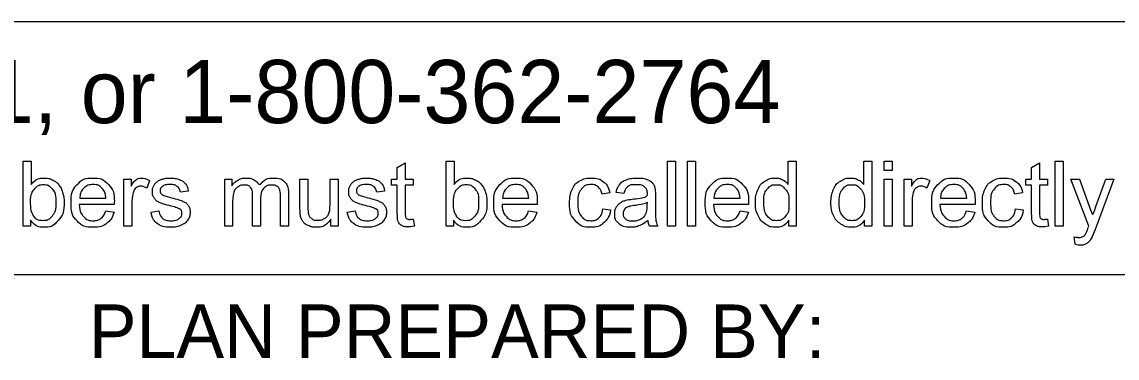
# Model space of a CAD drawing. Extents: x 0 to 96.2, y -27.5 to 31.3.
# Drawn here: x 45.936 to 48.797, y 1.82 to 2.697 of the extents above; entities that cross this region are included whole.
import ezdxf

# ---------------------------------------------------------------- set-up
doc = ezdxf.new("R2010")
doc.units = 0
doc.layers.add('TB1', color=7, linetype='Continuous')

msp = doc.modelspace()

# ---------------------------------------------------------------- linework, layer by layer
at = {"layer": 'TB1'}
for p, q in [((49.4609, 2.6972), (44.2359, 2.6972)), ((49.4609, 2.0372), (44.2359, 2.0372))]:
    msp.add_line(p, q, dxfattribs=at)
for points in [[(45.9585, 2.1641), (45.9393, 2.1641), (45.9393, 2.3335), (45.9601, 2.3335), (45.9601, 2.2731)], [(46.9163, 2.2001), (46.9163, 2.2708), (46.901, 2.2708), (46.901, 2.2869), (46.9163, 2.2869), (46.9163, 2.3173), (46.9371, 2.3298), (46.9371, 2.2869), (46.9579, 2.2869), (46.9579, 2.2708), (46.9371, 2.2708), (46.9371, 2.1988)], [(47.0631, 2.1641), (47.0439, 2.1641), (47.0439, 2.3335), (47.0647, 2.3335), (47.0647, 2.2731)], [(47.6223, 2.1641), (47.6223, 2.3335), (47.6431, 2.3335), (47.6431, 2.1641), (47.6223, 2.1641)], [(47.6749, 2.1641), (47.6749, 2.3335), (47.6957, 2.3335), (47.6957, 2.1641), (47.6749, 2.1641)], [(47.9376, 2.2728), (47.9376, 2.3335), (47.9584, 2.3335), (47.9584, 2.1641), (47.9392, 2.1641)], [(48.1349, 2.2728), (48.1349, 2.3335), (48.1557, 2.3335), (48.1557, 2.1641), (48.1365, 2.1641)], [(48.1885, 2.3096), (48.1885, 2.3335), (48.2093, 2.3335), (48.2093, 2.3096), (48.1885, 2.3096)], [(48.5734, 2.2001), (48.5734, 2.2708), (48.558, 2.2708), (48.558, 2.2869), (48.5734, 2.2869), (48.5734, 2.3173), (48.5942, 2.3298), (48.5942, 2.2869), (48.615, 2.2869), (48.615, 2.2708), (48.5942, 2.2708), (48.5942, 2.1988)], [(48.6349, 2.1641), (48.6349, 2.3335), (48.6556, 2.3335), (48.6556, 2.1641), (48.6349, 2.1641)], [(46.2023, 2.1641), (46.2023, 2.2869), (46.221, 2.2869), (46.221, 2.2683)], [(46.2689, 2.283), (46.2617, 2.2637)], [(46.4654, 2.1641), (46.4654, 2.2869), (46.484, 2.2869), (46.484, 2.2696)], [(46.6621, 2.2109), (46.6621, 2.2869), (46.6829, 2.2869), (46.6829, 2.2189)], [(46.7407, 2.2212), (46.7407, 2.2869), (46.7615, 2.2869), (46.7615, 2.1641), (46.7429, 2.1641)], [(48.1885, 2.1641), (48.1885, 2.2869), (48.2093, 2.2869), (48.2093, 2.1641), (48.1885, 2.1641)], [(48.2407, 2.1641), (48.2407, 2.2869), (48.2594, 2.2869), (48.2594, 2.2683)], [(48.3073, 2.283), (48.3, 2.2637)], [(48.7227, 2.164), (48.676, 2.2869), (48.6985, 2.2869), (48.724, 2.216)], [(48.7415, 2.2153), (48.7677, 2.2869), (48.7885, 2.2869), (48.7419, 2.162)], [(46.0866, 2.2372), (46.1552, 2.2372)], [(46.3704, 2.2551), (46.35, 2.2524)], [(46.5592, 2.2354), (46.5592, 2.1641), (46.5384, 2.1641), (46.5384, 2.2438)], [(46.6319, 2.2484), (46.6319, 2.1641), (46.6111, 2.1641), (46.6111, 2.2414)], [(46.8833, 2.2551), (46.8629, 2.2524)], [(47.1912, 2.2372), (47.2598, 2.2372)], [(47.4715, 2.2508), (47.4512, 2.2477)], [(47.5082, 2.2491), (47.4878, 2.2518)], [(47.5906, 2.2433), (47.5906, 2.2156)], [(47.7436, 2.2372), (47.8121, 2.2372)], [(48.3353, 2.2372), (48.4039, 2.2372)], [(48.5499, 2.2508), (48.5296, 2.2477)], [(46.177, 2.2202), (46.0855, 2.2202)], [(46.155, 2.2038), (46.1764, 2.201)], [(46.2231, 2.2284), (46.2231, 2.1641), (46.2023, 2.1641)], [(46.2729, 2.2008), (46.2935, 2.204)], [(46.4862, 2.2278), (46.4862, 2.1641), (46.4654, 2.1641)], [(46.7858, 2.2008), (46.8063, 2.204)], [(47.2816, 2.2202), (47.19, 2.2202)], [(47.2595, 2.2038), (47.281, 2.201)], [(47.4531, 2.209), (47.4735, 2.2063)], [(47.5695, 2.2181), (47.5696, 2.2257)], [(47.834, 2.2202), (47.7424, 2.2202)], [(47.8119, 2.2038), (47.8334, 2.201)], [(48.2615, 2.2284), (48.2615, 2.1641), (48.2407, 2.1641)], [(48.4257, 2.2202), (48.3341, 2.2202)], [(48.4036, 2.2038), (48.4251, 2.201)], [(48.5314, 2.209), (48.5518, 2.2063)], [(45.9585, 2.1795), (45.9585, 2.1641)], [(46.7429, 2.1641), (46.7429, 2.1822)], [(46.9579, 2.1827), (46.9609, 2.1643)], [(47.0631, 2.1795), (47.0631, 2.1641)], [(47.9392, 2.1641), (47.9392, 2.1796)], [(48.1365, 2.1641), (48.1365, 2.1796)], [(48.615, 2.1827), (48.6179, 2.1643)], [(47.5972, 2.1641), (47.5755, 2.1641)], [(48.687, 2.117), (48.6847, 2.1365)]]:
    msp.add_lwpolyline(points, dxfattribs=at)
for points, degree in [([(45.9601, 2.2731), (45.9733, 2.2896), (45.9937, 2.2896), (46.005, 2.2896), (46.0151, 2.2851), (46.0252, 2.2805), (46.0318, 2.2722), (46.0383, 2.264), (46.042, 2.2523), (46.0457, 2.2406), (46.0457, 2.2274), (46.0457, 2.1958), (46.0301, 2.1786), (46.0145, 2.1614), (45.9926, 2.1614), (45.9709, 2.1614), (45.9585, 2.1795)], 3), ([(46.1764, 2.201), (46.1714, 2.1822), (46.1576, 2.1718), (46.1439, 2.1614), (46.1225, 2.1614), (46.0956, 2.1614), (46.0798, 2.178), (46.064, 2.1946), (46.064, 2.2245), (46.064, 2.2554), (46.08, 2.2725), (46.0959, 2.2896), (46.1213, 2.2896), (46.1459, 2.2896), (46.1615, 2.2729), (46.1771, 2.2561), (46.1771, 2.2257), (46.1771, 2.2238), (46.177, 2.2202)], 3), ([(46.221, 2.2683), (46.2282, 2.2813), (46.2342, 2.2855), (46.2403, 2.2896), (46.2476, 2.2896), (46.2581, 2.2896), (46.2689, 2.283)], 3), ([(46.2935, 2.204), (46.2952, 2.1916), (46.3031, 2.185), (46.3111, 2.1784), (46.3253, 2.1784), (46.3397, 2.1784), (46.3467, 2.1843), (46.3536, 2.1901), (46.3536, 2.198), (46.3536, 2.2051), (46.3475, 2.2091), (46.3432, 2.2119), (46.3262, 2.2162), (46.3033, 2.222), (46.2944, 2.2262), (46.2856, 2.2304), (46.281, 2.2378), (46.2764, 2.2453), (46.2764, 2.2543), (46.2764, 2.2625), (46.2802, 2.2695), (46.2839, 2.2765), (46.2904, 2.2811), (46.2953, 2.2847), (46.3037, 2.2871), (46.3121, 2.2896), (46.3217, 2.2896), (46.3362, 2.2896), (46.3471, 2.2855), (46.358, 2.2813), (46.3632, 2.2742), (46.3685, 2.2671), (46.3704, 2.2551)], 3), ([(46.484, 2.2696), (46.4898, 2.2786), (46.4994, 2.2841), (46.509, 2.2896), (46.5212, 2.2896), (46.5349, 2.2896), (46.5436, 2.2839), (46.5523, 2.2783), (46.5559, 2.2681), (46.5705, 2.2896), (46.5939, 2.2896), (46.6122, 2.2896), (46.622, 2.2795), (46.6319, 2.2694), (46.6319, 2.2484)], 3), ([(46.8063, 2.204), (46.8081, 2.1916), (46.816, 2.185), (46.8239, 2.1784), (46.8382, 2.1784), (46.8526, 2.1784), (46.8595, 2.1843), (46.8665, 2.1901), (46.8665, 2.198), (46.8665, 2.2051), (46.8603, 2.2091), (46.856, 2.2119), (46.839, 2.2162), (46.8161, 2.222), (46.8073, 2.2262), (46.7984, 2.2304), (46.7938, 2.2378), (46.7893, 2.2453), (46.7893, 2.2543), (46.7893, 2.2625), (46.793, 2.2695), (46.7968, 2.2765), (46.8033, 2.2811), (46.8081, 2.2847), (46.8165, 2.2871), (46.8249, 2.2896), (46.8345, 2.2896), (46.849, 2.2896), (46.8599, 2.2855), (46.8709, 2.2813), (46.8761, 2.2742), (46.8813, 2.2671), (46.8833, 2.2551)], 3), ([(47.0647, 2.2731), (47.0778, 2.2896), (47.0983, 2.2896), (47.1096, 2.2896), (47.1197, 2.2851), (47.1298, 2.2805), (47.1364, 2.2722), (47.1429, 2.264), (47.1466, 2.2523), (47.1503, 2.2406), (47.1503, 2.2274), (47.1503, 2.1958), (47.1347, 2.1786), (47.1191, 2.1614), (47.0972, 2.1614), (47.0755, 2.1614), (47.0631, 2.1795)], 3), ([(47.281, 2.201), (47.2759, 2.1822), (47.2622, 2.1718), (47.2484, 2.1614), (47.2271, 2.1614), (47.2002, 2.1614), (47.1844, 2.178), (47.1686, 2.1946), (47.1686, 2.2245), (47.1686, 2.2554), (47.1846, 2.2725), (47.2005, 2.2896), (47.2259, 2.2896), (47.2505, 2.2896), (47.2661, 2.2729), (47.2817, 2.2561), (47.2817, 2.2257), (47.2817, 2.2238), (47.2816, 2.2202)], 3), ([(47.4735, 2.2063), (47.4701, 2.1853), (47.4563, 2.1733), (47.4425, 2.1614), (47.4224, 2.1614), (47.3972, 2.1614), (47.3819, 2.1779), (47.3665, 2.1943), (47.3665, 2.225), (47.3665, 2.2449), (47.3731, 2.2598), (47.3797, 2.2747), (47.3932, 2.2822), (47.4067, 2.2896), (47.4225, 2.2896), (47.4425, 2.2896), (47.4552, 2.2795), (47.4679, 2.2694), (47.4715, 2.2508)], 3), ([(47.4878, 2.2518), (47.4906, 2.2649), (47.4969, 2.2729), (47.5033, 2.2809), (47.5153, 2.2853), (47.5273, 2.2896), (47.5431, 2.2896), (47.5588, 2.2896), (47.5686, 2.2859), (47.5784, 2.2822), (47.5831, 2.2766), (47.5877, 2.271), (47.5895, 2.2624), (47.5906, 2.2571), (47.5906, 2.2433)], 3), ([(47.8334, 2.201), (47.8283, 2.1822), (47.8146, 2.1718), (47.8008, 2.1614), (47.7794, 2.1614), (47.7525, 2.1614), (47.7367, 2.178), (47.721, 2.1946), (47.721, 2.2245), (47.721, 2.2554), (47.7369, 2.2725), (47.7529, 2.2896), (47.7783, 2.2896), (47.8029, 2.2896), (47.8185, 2.2729), (47.8341, 2.2561), (47.8341, 2.2257), (47.8341, 2.2238), (47.834, 2.2202)], 3), ([(47.9392, 2.1796), (47.9275, 2.1614), (47.9048, 2.1614), (47.8902, 2.1614), (47.8779, 2.1695), (47.8655, 2.1776), (47.8588, 2.1921), (47.852, 2.2066), (47.852, 2.2254), (47.852, 2.2438), (47.8581, 2.2587), (47.8643, 2.2737), (47.8765, 2.2816), (47.8887, 2.2896), (47.9038, 2.2896), (47.9149, 2.2896), (47.9236, 2.2849), (47.9322, 2.2803), (47.9376, 2.2728)], 3), ([(48.1365, 2.1796), (48.1248, 2.1614), (48.1021, 2.1614), (48.0875, 2.1614), (48.0751, 2.1695), (48.0628, 2.1776), (48.0561, 2.1921), (48.0493, 2.2066), (48.0493, 2.2254), (48.0493, 2.2438), (48.0554, 2.2587), (48.0615, 2.2737), (48.0738, 2.2816), (48.086, 2.2896), (48.1011, 2.2896), (48.1122, 2.2896), (48.1208, 2.2849), (48.1295, 2.2803), (48.1349, 2.2728)], 3), ([(48.2594, 2.2683), (48.2665, 2.2813), (48.2726, 2.2855), (48.2787, 2.2896), (48.2859, 2.2896), (48.2964, 2.2896), (48.3073, 2.283)], 3), ([(48.4251, 2.201), (48.42, 2.1822), (48.4063, 2.1718), (48.3925, 2.1614), (48.3712, 2.1614), (48.3443, 2.1614), (48.3285, 2.178), (48.3127, 2.1946), (48.3127, 2.2245), (48.3127, 2.2554), (48.3287, 2.2725), (48.3446, 2.2896), (48.37, 2.2896), (48.3946, 2.2896), (48.4102, 2.2729), (48.4258, 2.2561), (48.4258, 2.2257), (48.4258, 2.2238), (48.4257, 2.2202)], 3), ([(48.5518, 2.2063), (48.5485, 2.1853), (48.5347, 2.1733), (48.5209, 2.1614), (48.5007, 2.1614), (48.4756, 2.1614), (48.4602, 2.1779), (48.4449, 2.1943), (48.4449, 2.225), (48.4449, 2.2449), (48.4515, 2.2598), (48.4581, 2.2747), (48.4716, 2.2822), (48.485, 2.2896), (48.5009, 2.2896), (48.5209, 2.2896), (48.5336, 2.2795), (48.5463, 2.2694), (48.5499, 2.2508)], 3), ([(45.9583, 2.2264), (45.9583, 2.2043), (45.9643, 2.1945), (45.9741, 2.1784), (45.9908, 2.1784), (46.0044, 2.1784), (46.0143, 2.1903), (46.0243, 2.2022), (46.0243, 2.2256), (46.0243, 2.2497), (46.0147, 2.2611), (46.0052, 2.2726), (45.9917, 2.2726), (45.9781, 2.2726), (45.9682, 2.2607), (45.9583, 2.2489), (45.9583, 2.2264)], 3), ([(46.1552, 2.2372), (46.1538, 2.2527), (46.1473, 2.2605), (46.1374, 2.2726), (46.1215, 2.2726), (46.1072, 2.2726), (46.0974, 2.2629), (46.0877, 2.2533), (46.0866, 2.2372)], 3), ([(46.2617, 2.2637), (46.2541, 2.2682), (46.2465, 2.2682), (46.2397, 2.2682), (46.2343, 2.2641), (46.2289, 2.26), (46.2266, 2.2527), (46.2231, 2.2416), (46.2231, 2.2284)], 3), ([(46.35, 2.2524), (46.3486, 2.2619), (46.342, 2.2672), (46.3353, 2.2726), (46.3232, 2.2726), (46.3088, 2.2726), (46.3027, 2.2678), (46.2966, 2.2631), (46.2966, 2.2567), (46.2966, 2.2527), (46.2991, 2.2494), (46.3017, 2.2461), (46.3071, 2.2439), (46.3102, 2.2427), (46.3255, 2.2385), (46.3476, 2.2326), (46.3563, 2.2289), (46.3651, 2.2251), (46.3701, 2.218), (46.3751, 2.2108), (46.3751, 2.2002), (46.3751, 2.1898), (46.369, 2.1806), (46.3629, 2.1715), (46.3514, 2.1664), (46.34, 2.1614), (46.3255, 2.1614), (46.3015, 2.1614), (46.289, 2.1713), (46.2764, 2.1813), (46.2729, 2.2008)], 3), ([(46.5384, 2.2438), (46.5384, 2.2577), (46.5333, 2.2646), (46.5282, 2.2715), (46.5166, 2.2715), (46.5078, 2.2715), (46.5004, 2.2669), (46.4929, 2.2623), (46.4896, 2.2534), (46.4862, 2.2445), (46.4862, 2.2278)], 3), ([(46.6111, 2.2414), (46.6111, 2.2539), (46.609, 2.2594), (46.607, 2.2648), (46.6017, 2.2682), (46.5964, 2.2715), (46.5892, 2.2715), (46.5763, 2.2715), (46.5677, 2.2629), (46.5592, 2.2543), (46.5592, 2.2354)], 3), ([(46.8629, 2.2524), (46.8615, 2.2619), (46.8548, 2.2672), (46.8482, 2.2726), (46.836, 2.2726), (46.8217, 2.2726), (46.8155, 2.2678), (46.8094, 2.2631), (46.8094, 2.2567), (46.8094, 2.2527), (46.812, 2.2494), (46.8145, 2.2461), (46.8199, 2.2439), (46.8231, 2.2427), (46.8383, 2.2385), (46.8604, 2.2326), (46.8692, 2.2289), (46.8779, 2.2251), (46.8829, 2.218), (46.8879, 2.2108), (46.8879, 2.2002), (46.8879, 2.1898), (46.8818, 2.1806), (46.8758, 2.1715), (46.8643, 2.1664), (46.8528, 2.1614), (46.8384, 2.1614), (46.8144, 2.1614), (46.8018, 2.1713), (46.7893, 2.1813), (46.7858, 2.2008)], 3), ([(47.0629, 2.2264), (47.0629, 2.2043), (47.0689, 2.1945), (47.0787, 2.1784), (47.0954, 2.1784), (47.109, 2.1784), (47.1189, 2.1903), (47.1288, 2.2022), (47.1288, 2.2256), (47.1288, 2.2497), (47.1193, 2.2611), (47.1098, 2.2726), (47.0963, 2.2726), (47.0827, 2.2726), (47.0728, 2.2607), (47.0629, 2.2489), (47.0629, 2.2264)], 3), ([(47.2598, 2.2372), (47.2584, 2.2527), (47.2519, 2.2605), (47.242, 2.2726), (47.2261, 2.2726), (47.2118, 2.2726), (47.202, 2.2629), (47.1923, 2.2533), (47.1912, 2.2372)], 3), ([(47.4512, 2.2477), (47.4484, 2.2601), (47.441, 2.2663), (47.4337, 2.2726), (47.4233, 2.2726), (47.4076, 2.2726), (47.3978, 2.2613), (47.388, 2.25), (47.388, 2.2256), (47.388, 2.2009), (47.3975, 2.1897), (47.4069, 2.1784), (47.4222, 2.1784), (47.4344, 2.1784), (47.4427, 2.186), (47.4509, 2.1935), (47.4531, 2.209)], 3), ([(47.5713, 2.1792), (47.5597, 2.1695), (47.549, 2.1654), (47.5384, 2.1614), (47.5261, 2.1614), (47.5059, 2.1614), (47.495, 2.1713), (47.4842, 2.1811), (47.4842, 2.1965), (47.4842, 2.2055), (47.4883, 2.2129), (47.4924, 2.2204), (47.499, 2.2249), (47.5057, 2.2294), (47.514, 2.2317), (47.5201, 2.2333), (47.5325, 2.2348), (47.5576, 2.2378), (47.5695, 2.242), (47.5696, 2.2463), (47.5696, 2.2474), (47.5696, 2.2602), (47.5638, 2.2654), (47.5558, 2.2724), (47.5401, 2.2724), (47.5255, 2.2724), (47.5185, 2.2673), (47.5115, 2.2621), (47.5082, 2.2491)], 3), ([(47.8121, 2.2372), (47.8107, 2.2527), (47.8043, 2.2605), (47.7943, 2.2726), (47.7785, 2.2726), (47.7641, 2.2726), (47.7544, 2.2629), (47.7446, 2.2533), (47.7436, 2.2372)], 3), ([(47.8735, 2.2254), (47.8735, 2.2018), (47.8834, 2.1901), (47.8933, 2.1784), (47.9069, 2.1784), (47.9205, 2.1784), (47.93, 2.1896), (47.9396, 2.2008), (47.9396, 2.2237), (47.9396, 2.2489), (47.9299, 2.2607), (47.9201, 2.2724), (47.9059, 2.2724), (47.8921, 2.2724), (47.8828, 2.2611), (47.8735, 2.2498), (47.8735, 2.2254)], 3), ([(48.0707, 2.2254), (48.0707, 2.2018), (48.0807, 2.1901), (48.0906, 2.1784), (48.1041, 2.1784), (48.1178, 2.1784), (48.1273, 2.1896), (48.1369, 2.2008), (48.1369, 2.2237), (48.1369, 2.2489), (48.1271, 2.2607), (48.1174, 2.2724), (48.1032, 2.2724), (48.0894, 2.2724), (48.0801, 2.2611), (48.0707, 2.2498), (48.0707, 2.2254)], 3), ([(48.3, 2.2637), (48.2924, 2.2682), (48.2848, 2.2682), (48.278, 2.2682), (48.2726, 2.2641), (48.2672, 2.26), (48.2649, 2.2527), (48.2615, 2.2416), (48.2615, 2.2284)], 3), ([(48.4039, 2.2372), (48.4025, 2.2527), (48.396, 2.2605), (48.3861, 2.2726), (48.3702, 2.2726), (48.3559, 2.2726), (48.3461, 2.2629), (48.3363, 2.2533), (48.3353, 2.2372)], 3), ([(48.5296, 2.2477), (48.5267, 2.2601), (48.5194, 2.2663), (48.5121, 2.2726), (48.5017, 2.2726), (48.486, 2.2726), (48.4762, 2.2613), (48.4664, 2.25), (48.4664, 2.2256), (48.4664, 2.2009), (48.4758, 2.1897), (48.4853, 2.1784), (48.5006, 2.1784), (48.5128, 2.1784), (48.521, 2.186), (48.5292, 2.1935), (48.5314, 2.209)], 3), ([(46.0855, 2.2202), (46.0866, 2.1999), (46.0969, 2.1892), (46.1072, 2.1784), (46.1226, 2.1784), (46.134, 2.1784), (46.1421, 2.1845), (46.1502, 2.1905), (46.155, 2.2038)], 3), ([(46.7429, 2.1822), (46.7286, 2.1614), (46.704, 2.1614), (46.6932, 2.1614), (46.6837, 2.1656), (46.6743, 2.1697), (46.6698, 2.176), (46.6652, 2.1823), (46.6634, 2.1914), (46.6621, 2.1976), (46.6621, 2.2109)], 3), ([(46.6829, 2.2189), (46.6829, 2.2026), (46.6842, 2.1969), (46.6861, 2.1887), (46.6925, 2.184), (46.6988, 2.1794), (46.7082, 2.1794), (46.7175, 2.1794), (46.7257, 2.1841), (46.7339, 2.1889), (46.7373, 2.1972), (46.7407, 2.2055), (46.7407, 2.2212)], 3), ([(47.19, 2.2202), (47.1912, 2.1999), (47.2015, 2.1892), (47.2118, 2.1784), (47.2272, 2.1784), (47.2386, 2.1784), (47.2467, 2.1845), (47.2548, 2.1905), (47.2595, 2.2038)], 3), ([(47.5696, 2.2257), (47.5583, 2.2211), (47.5356, 2.2179), (47.5228, 2.216), (47.5175, 2.2137), (47.5122, 2.2114), (47.5093, 2.2069), (47.5064, 2.2025), (47.5064, 2.1971), (47.5064, 2.1888), (47.5127, 2.1832), (47.519, 2.1777), (47.5311, 2.1777), (47.5431, 2.1777), (47.5524, 2.1829), (47.5618, 2.1882), (47.5662, 2.1973), (47.5695, 2.2043), (47.5695, 2.2181)], 3), ([(47.5906, 2.2156), (47.5906, 2.1866), (47.5919, 2.1789), (47.5932, 2.1712), (47.5972, 2.1641)], 3), ([(47.7424, 2.2202), (47.7436, 2.1999), (47.7539, 2.1892), (47.7641, 2.1784), (47.7795, 2.1784), (47.791, 2.1784), (47.7991, 2.1845), (47.8072, 2.1905), (47.8119, 2.2038)], 3), ([(48.3341, 2.2202), (48.3353, 2.1999), (48.3456, 2.1892), (48.3559, 2.1784), (48.3713, 2.1784), (48.3827, 2.1784), (48.3908, 2.1845), (48.3989, 2.1905), (48.4036, 2.2038)], 3), ([(48.724, 2.216), (48.729, 2.2026), (48.7329, 2.1877), (48.7365, 2.2017), (48.7415, 2.2153)], 3), ([(46.9609, 2.1643), (46.9521, 2.1624), (46.9452, 2.1624), (46.9339, 2.1624), (46.9276, 2.166), (46.9214, 2.1696), (46.9189, 2.1755), (46.9163, 2.1813), (46.9163, 2.2001)], 3), ([(46.9371, 2.1988), (46.9371, 2.1899), (46.9382, 2.1874), (46.9393, 2.1848), (46.9418, 2.1833), (46.9442, 2.1818), (46.9488, 2.1818), (46.9523, 2.1818), (46.9579, 2.1827)], 3), ([(47.5755, 2.1641), (47.5722, 2.1706), (47.5713, 2.1792)], 2), ([(48.6179, 2.1643), (48.6092, 2.1624), (48.6022, 2.1624), (48.5909, 2.1624), (48.5847, 2.166), (48.5785, 2.1696), (48.5759, 2.1755), (48.5734, 2.1813), (48.5734, 2.2001)], 3), ([(48.5942, 2.1988), (48.5942, 2.1899), (48.5953, 2.1874), (48.5964, 2.1848), (48.5988, 2.1833), (48.6013, 2.1818), (48.6059, 2.1818), (48.6093, 2.1818), (48.615, 2.1827)], 3), ([(48.6847, 2.1365), (48.6915, 2.1347), (48.6966, 2.1347), (48.7035, 2.1347), (48.7077, 2.137), (48.7118, 2.1393), (48.7145, 2.1435), (48.7164, 2.1466), (48.7208, 2.1589), (48.7214, 2.1607), (48.7227, 2.164)], 3), ([(48.7419, 2.162), (48.7344, 2.1418), (48.7303, 2.1342), (48.7247, 2.124), (48.7175, 2.1192), (48.7104, 2.1144), (48.7004, 2.1144), (48.6944, 2.1144), (48.687, 2.117)], 3)]:
    msp.add_open_spline(points, degree=degree, dxfattribs=at)

# ---------------------------------------------------------------- texts
for s, height, p in [('OHIO811, 8-1-1, or 1-800-362-2764', 0.165, (44.397, 2.433)), ('PLAN PREPARED BY:', 0.14, (46.1103, 1.8197))]:
    msp.add_text(s, height=height, dxfattribs=at).set_placement(p)

doc.saveas('drawing.dxf')
